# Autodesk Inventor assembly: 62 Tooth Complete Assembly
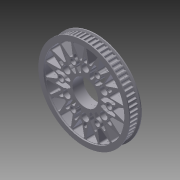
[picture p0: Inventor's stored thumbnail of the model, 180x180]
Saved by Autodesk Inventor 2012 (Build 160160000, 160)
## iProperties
Created: 2013-01
Part Number: 62 Tooth Complete Assembly
Document SubType Name: Assembly
Designer: Jeff
Mass: 103.452 g
Surface Area: 448.975 cm^2
Volume: 38.334 cm^3
Density: 2.69871 g/cm^3
Author: Jeff
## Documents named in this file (3)
- C:\Users\Owner\Documents\Robotics\Mechanical Design\Parts\pulley\HTD\9mm\Double Flange\62 Tooth\62 Tooth Complete Assembly.iam
- C:\Users\Owner\Documents\Robotics\Mechanical Design\Parts\pulley\HTD\9mm\Double Flange\62 Tooth\62 Tooth .22 Thickness.iam
- C:\Users\Owner\Documents\Robotics\Mechanical Design\Parts\pulley\HTD\9mm\Double Flange\62 Tooth\62 Tooth.32 Thickness.iam
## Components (2 placed, 2 different names)
1. 62 Tooth .22 Thickness:1 [sub-assembly] — Mate:3, Mate:4, Angle:1, Flush:1
2. 62 Tooth.32 Thickness:1 [sub-assembly] — Mate:3, Mate:4, Angle:1
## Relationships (4: Mate 2, Angle 1, Flush 1)
- Mate:3: 62 Tooth .22 Thickness:1 ↔ 62 Tooth.32 Thickness:1
- Mate:4: 62 Tooth .22 Thickness:1 ↔ 62 Tooth.32 Thickness:1
- Angle:1: 62 Tooth .22 Thickness:1 ↔ 62 Tooth.32 Thickness:1
- Flush:1: 62 Tooth .22 Thickness:1
